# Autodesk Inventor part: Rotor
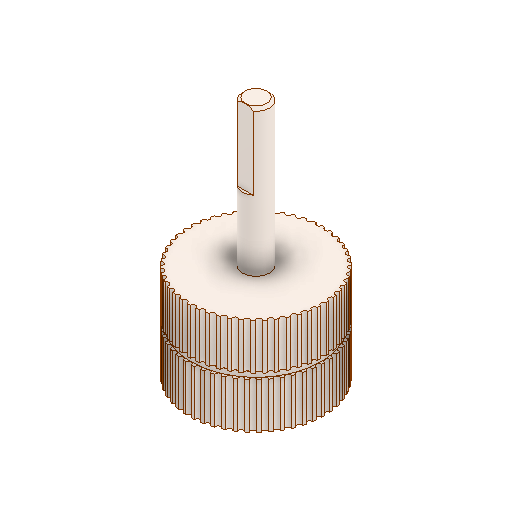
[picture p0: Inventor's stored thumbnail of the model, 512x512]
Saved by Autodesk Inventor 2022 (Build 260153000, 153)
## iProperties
Created: 2020-10
Part Number: Rotor
Material: Generico
Document SubType Name: Modeling
Designer: admin
Density: 1 g/cm^3
Appearance: Default
Author: admin
Sending System: SolidWorks 2020
Last Author: Simon
Last Saved: 2020-10-29
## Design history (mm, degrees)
combine "Combine1"
node "Solido1"
